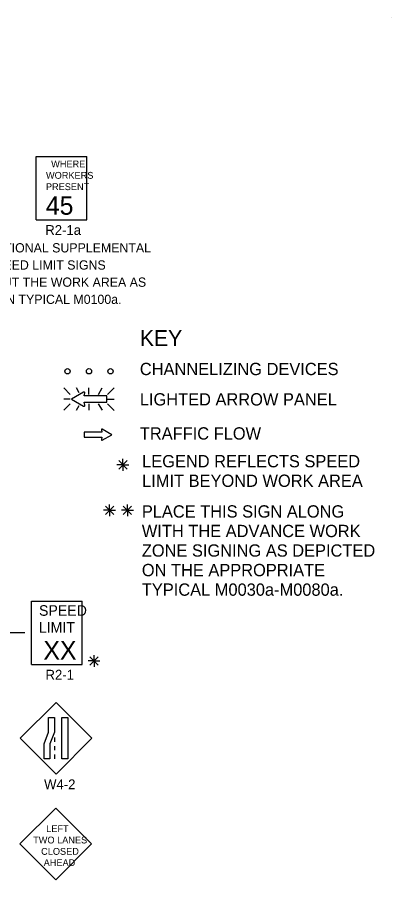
# Model space of a CAD drawing. Extents: x 16590 to 19504, y 5703 to 6974.
# Drawn here: x 18169 to 18453, y 6278 to 6931 of the extents above; entities that cross this region are included whole.
import ezdxf

# ---------------------------------------------------------------- set-up
doc = ezdxf.new("R2010")
doc.units = 0
for name, color, linetype in [('BORDER', 7, 'Continuous'), ('MT_SCRATCH_LEVEL_E', 7, 'Continuous'), ('TRAFFIC_SIGNS_PR', 7, 'Continuous'), ('TYPICAL_TEXT_DIMEN_EX', 7, 'Continuous'), ('TYPICAL_TEXT_DIMEN_PR', 7, 'Continuous')]:
    doc.layers.add(name, color=color, linetype=linetype)

msp = doc.modelspace()

# ---------------------------------------------------------------- linework, layer by layer
at = {"layer": 'BORDER'}
msp.add_line((18452.55, 6930.8), (18452.55, 6930.8), dxfattribs=at)
msp.add_line((18452.55, 6930.8), (18452.55, 6930.8), dxfattribs=at)
at = {"layer": 'MT_SCRATCH_LEVEL_E'}
for p, q in [((18232.77, 6616.55), (18219.52, 6616.55)), ((18219.52, 6616.55), (18219.52, 6612.81)), ((18232.46, 6618.33), (18232.77, 6616.55)), ((18240.38, 6614.7), (18233.14, 6618.81)), ((18219.52, 6612.81), (18232.77, 6612.81)), ((18232.77, 6612.81), (18232.46, 6611.03)), ((18233.14, 6610.55), (18240.38, 6614.7))]:
    msp.add_line(p, q, dxfattribs=at)
for centre, start, end in [((18232.92, 6618.4), 60.42484, 189.96381), ((18232.92, 6610.96), 170.03619, 299.77312)]:
    msp.add_arc(centre, 0.463, start, end, dxfattribs=at)
at = {"layer": 'TRAFFIC_SIGNS_PR'}
for p, q in [((18183.08, 6825.41), (18221.48, 6825.41)), ((18183.08, 6777.41), (18183.08, 6825.41)), ((18221.48, 6777.41), (18221.48, 6825.41)), ((18183.08, 6777.41), (18221.48, 6777.41)), ((18203.97, 6650.12), (18208.9, 6645.19)), ((18215.73, 6646.3), (18213.52, 6650.13)), ((18223.05, 6645.19), (18223.05, 6650.13)), ((18230.29, 6645.19), (18233.14, 6650.13)), ((18237.2, 6645.19), (18242.14, 6650.13)), ((18208.9, 6641.64), (18203.97, 6641.64)), ((18203.97, 6633.15), (18208.9, 6638.08)), ((18213.48, 6633.15), (18215.59, 6636.81)), ((18223.05, 6638.08), (18223.05, 6633.15)), ((18233.18, 6633.15), (18230.33, 6638.08)), ((18237.2, 6641.64), (18242.14, 6641.64)), ((18237.2, 6638.08), (18242.14, 6633.14)), ((18179.4, 6488.72), (18217.85, 6488.72)), ((18179.4, 6440.66), (18179.4, 6488.72)), ((18217.85, 6440.66), (18217.85, 6488.72)), ((18179.4, 6440.66), (18217.85, 6440.66)), ((18198.08, 6411.99), (18170.92, 6384.84)), ((18225.23, 6384.84), (18198.08, 6411.99)), ((18170.92, 6384.84), (18198.08, 6357.68)), ((18196.83, 6385.33), (18196.83, 6382.13)), ((18198.08, 6357.68), (18225.23, 6384.84)), ((18196.83, 6378.93), (18196.83, 6375.73)), ((18196.83, 6372.53), (18196.83, 6369.33)), ((18197.82, 6331.99), (18170.67, 6304.84)), ((18224.97, 6304.84), (18197.82, 6331.99)), ((18170.67, 6304.84), (18197.82, 6277.68)), ((18197.82, 6277.68), (18224.97, 6304.84))]:
    msp.add_line(p, q, dxfattribs=at)
for points in [[(18218.98, 6646.91), (18209.69, 6641.64), (18218.98, 6636.32)], [(18219.85, 6636.94), (18219.45, 6639.21), (18236.47, 6639.21), (18236.47, 6644.01), (18219.45, 6644.01), (18219.86, 6646.29)]]:
    msp.add_lwpolyline(points, dxfattribs=at)
for points in [[(18196.83, 6400.57), (18196.83, 6389.39), (18193.48, 6380.51), (18193.48, 6369.33), (18188.99, 6369.33), (18188.99, 6380.51), (18192.33, 6389.39), (18192.33, 6400.57)], [(18206.96, 6400.57), (18206.96, 6369.33), (18202.47, 6369.33), (18202.47, 6400.57)]]:
    msp.add_lwpolyline(points, close=True, dxfattribs=at)
for centre in [(18206.76, 6662.75), (18223.06, 6662.75), (18239.36, 6662.75)]:
    msp.add_circle(centre, 2, dxfattribs=at)
for centre, radius, start, end in [((18219.27, 6646.39), 0.598, 350.73078, 118.89165), ((18219.26, 6636.84), 0.597, 241.48329, 9.95933)]:
    msp.add_arc(centre, radius, start, end, dxfattribs=at)
at = {"layer": 'TYPICAL_TEXT_DIMEN_PR'}
for p, q in [((18248.8, 6591.88), (18244.27, 6591.88)), ((18245.61, 6595.06), (18251.99, 6588.69)), ((18251.99, 6595.06), (18245.61, 6588.69)), ((18248.8, 6591.88), (18248.8, 6596.33)), ((18248.8, 6591.88), (18251.99, 6591.88)), ((18248.8, 6591.88), (18253.28, 6591.88)), ((18248.8, 6591.88), (18248.8, 6587.38)), ((18238.7, 6557.48), (18234.17, 6557.48)), ((18235.51, 6560.66), (18241.89, 6554.29)), ((18241.89, 6560.66), (18235.51, 6554.29)), ((18238.7, 6557.48), (18238.7, 6561.93)), ((18238.7, 6557.48), (18241.89, 6557.48)), ((18238.7, 6557.48), (18243.18, 6557.48)), ((18238.7, 6557.48), (18238.7, 6552.98)), ((18252.2, 6557.48), (18247.67, 6557.48)), ((18249.02, 6560.66), (18255.39, 6554.29)), ((18255.39, 6560.66), (18249.02, 6554.29)), ((18252.2, 6557.48), (18252.2, 6561.93)), ((18252.2, 6557.48), (18255.39, 6557.48)), ((18252.2, 6557.48), (18256.68, 6557.48)), ((18252.2, 6557.48), (18252.2, 6552.98)), ((18079.39, 6464.84), (18174.5, 6464.84)), ((18223.72, 6446.6), (18230.09, 6440.23)), ((18230.09, 6446.6), (18223.72, 6440.23)), ((18226.91, 6443.42), (18226.91, 6447.87)), ((18226.91, 6443.42), (18222.37, 6443.42)), ((18226.91, 6443.42), (18230.09, 6443.42)), ((18226.91, 6443.42), (18231.38, 6443.42)), ((18226.91, 6443.42), (18226.91, 6438.92))]:
    msp.add_line(p, q, dxfattribs=at)
msp.add_open_spline([(18340.39, 6582.26), (18340.41, 6582.26), (18340.42, 6582.26), (18340.42, 6582.26)], degree=2, dxfattribs=at)

# ---------------------------------------------------------------- texts
at = {"layer": 'TRAFFIC_SIGNS_PR'}
for s, height, p in [('WHERE', 5.2, (18194.39, 6817.09)), ('WORKERS', 5.2, (18190.47, 6808.49)), ('PRESENT', 5.2, (18190.4, 6799.89)), ('45', 14.031, (18190.39, 6781.26)), ('R2-1a', 7.44, (18189.94, 6765.97)), ('PLACE ADDITIONAL SUPPLEMENTAL', 7, (18103.08, 6752.71)), ('SETS OF SPEED LIMIT SIGNS', 7, (18103.08, 6739.71)), ('THROUGHOUT THE WORK AREA AS', 7, (18103.08, 6726.71)), ('DEPICTED ON TYPICAL M0100a.', 7, (18103.08, 6713.71)), ('SPEED', 8.01, (18185.17, 6477.57)), ('LIMIT', 8.01, (18185.01, 6464.75)), ('XX', 14.048, (18188.52, 6444.42)), ('R2-1', 7.449, (18190.09, 6429.21)), ('W4-2', 7.44, (18189.03, 6346.24)), ('LEFT', 5.2, (18190.62, 6313.77)), ('TWO LANES', 5.2, (18180.73, 6305.17)), ('CLOSED', 5.2, (18186.78, 6296.57)), ('AHEAD', 5.2, (18188.71, 6287.97))]:
    msp.add_text(s, height=height, dxfattribs=at).set_placement(p)
at = {"layer": 'TYPICAL_TEXT_DIMEN_EX'}
for s, height, p in [('KEY', 12, (18261.6, 6681.86)), ('CHANNELIZING DEVICES', 9.3, (18261.6, 6659.81)), ('LIGHTED ARROW PANEL', 9.3, (18261.6, 6636.81)), ('TRAFFIC FLOW', 9.3, (18261.6, 6611.01)), ('LEGEND REFLECTS SPEED', 9.3, (18263.35, 6589.98)), ('LIMIT BEYOND WORK AREA', 9.3, (18263.35, 6575.18)), ('PLACE THIS SIGN ALONG', 9.3, (18263.11, 6551.94)), ('WITH THE ADVANCE WORK', 9.3, (18263.11, 6537.14)), ('ZONE SIGNING AS DEPICTED', 9.3, (18263.11, 6522.34)), ('ON THE APPROPRIATE', 9.3, (18263.11, 6507.54)), ('TYPICAL M0030a-M0080a.', 9.3, (18263.11, 6492.74))]:
    msp.add_text(s, height=height, dxfattribs=at).set_placement(p)

doc.saveas('drawing.dxf')
